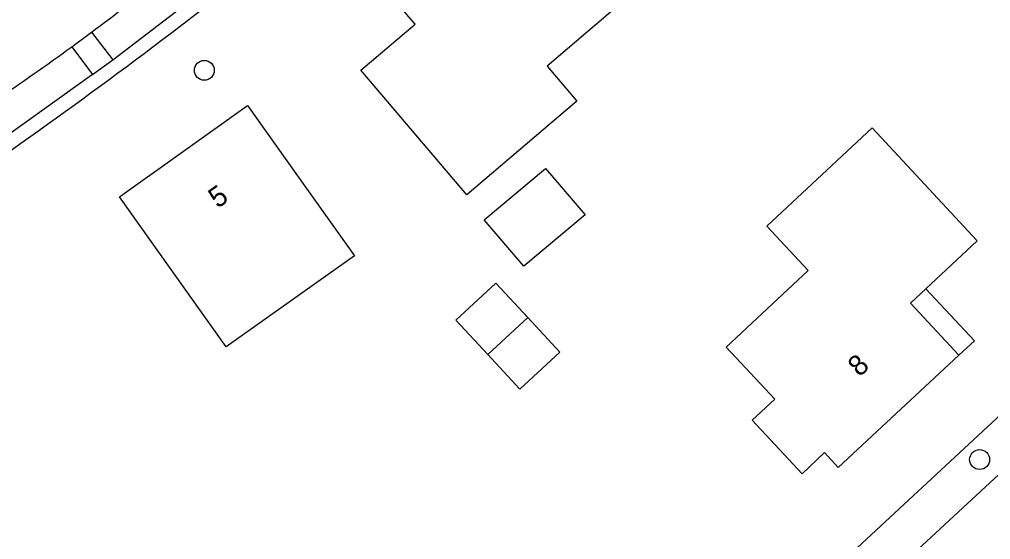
# Model space of a CAD drawing. Extents: x 162675 to 163482, y 379761 to 381227.
# Drawn here: x 163252.7 to 163300.37, y 380905.56 to 380931.1 of the extents above; entities that cross this region are included whole.
import ezdxf

# ---------------------------------------------------------------- set-up
doc = ezdxf.new("R2010")
doc.units = 0
for name, color, linetype in [('IMGEO_Berm_groen', 7, 'Continuous'), ('IMGEO_Boom', 7, 'Continuous'), ('IMGEO_Haag', 7, 'Continuous'), ('IMGEO_Pand', 7, 'Continuous'), ('IMGEO_Pand_nummerreeks', 7, 'Continuous'), ('IMGEO_Pand_overbouw', 7, 'Continuous'), ('IMGEO_Parkeervlak_halfverhard', 7, 'Continuous'), ('IMGEO_Rijbaan_lokaal_gesloten', 7, 'Continuous'), ('IMGEO_Voetpad_open', 7, 'Continuous')]:
    doc.layers.add(name, color=color, linetype=linetype)

msp = doc.modelspace()

# ---------------------------------------------------------------- linework, layer by layer
at = {"layer": 'IMGEO_Berm_groen'}
msp.add_lwpolyline([(163278.098, 380890.562), (163302.041, 380912.777)], dxfattribs=at)
at = {"layer": 'IMGEO_Boom'}
for centre in [(163261.779, 380928.597), (163299.834, 380909.487)]:
    msp.add_circle(centre, 0.489, dxfattribs=at)
at = {"layer": 'IMGEO_Haag'}
msp.add_arc((163095.383, 381147.201), 272.283, 301.26259, 308.46483, dxfattribs=at)
at = {"layer": 'IMGEO_Pand'}
for points in [[(163272.637, 380935.682), (163276.199, 380938.643), (163276.806, 380937.922), (163277.935, 380938.883), (163280.268, 380936.141), (163279.118, 380935.162), (163282.041, 380931.727), (163278.606, 380928.803), (163279.89, 380927.294), (163280.071, 380927.082), (163274.67, 380922.486), (163270.866, 380926.955), (163269.468, 380928.597), (163272.133, 380930.865), (163270.614, 380932.649), (163273.28, 380934.918), (163272.637, 380935.682)], [(163257.609, 380922.38), (163263.9, 380926.863), (163266.801, 380922.792), (163269.149, 380919.497), (163262.858, 380915.014), (163260.51, 380918.309), (163257.609, 380922.38)], [(163289.384, 380920.952), (163294.56, 380925.767), (163299.721, 380920.22), (163297.196, 380917.871), (163296.437, 380917.165), (163298.814, 380914.61), (163292.897, 380909.095), (163292.215, 380909.827), (163291.121, 380908.79), (163288.672, 380911.424), (163289.774, 380912.45), (163287.391, 380915.013), (163291.421, 380918.761), (163289.384, 380920.952)], [(163275.515, 380921.262), (163278.531, 380923.775), (163280.472, 380921.501), (163277.455, 380918.988), (163275.515, 380921.262)], [(163275.691, 380914.641), (163274.122, 380916.336), (163276.084, 380918.152), (163277.653, 380916.458)], [(163277.653, 380916.458), (163279.222, 380914.764), (163277.261, 380912.947), (163275.691, 380914.641)], [(163277.653, 380916.458), (163275.691, 380914.641)]]:
    msp.add_lwpolyline(points, dxfattribs=at)
at = {"layer": 'IMGEO_Pand_overbouw'}
msp.add_lwpolyline([(163298.814, 380914.61), (163299.575, 380915.314), (163297.196, 380917.871), (163296.437, 380917.165)], close=True, dxfattribs=at)
at = {"layer": 'IMGEO_Parkeervlak_halfverhard'}
for points in [[(163257.282, 380929.108), (163260.911, 380931.872)], [(163256.292, 380928.387), (163252.192, 380925.45)]]:
    msp.add_lwpolyline(points, dxfattribs=at)
at = {"layer": 'IMGEO_Rijbaan_lokaal_gesloten'}
for points in [[(163255.272, 380929.752), (163256.239, 380930.465)], [(163303.486, 380911.264), (163303.421, 380911.205), (163292.603, 380901.179), (163284.042, 380893.331), (163283.878, 380893.181), (163279.38, 380889.205)]]:
    msp.add_lwpolyline(points, dxfattribs=at)
for centre, radius, start, end in [((163184.857, 381026.102), 119.339, 306.73702, 308.85086), ((163187.054, 381023.259), 115.746, 303.81288, 306.11255)]:
    msp.add_arc(centre, radius, start, end, dxfattribs=at)
at = {"layer": 'IMGEO_Voetpad_open'}
for points in [[(163256.239, 380930.465), (163257.282, 380929.108)], [(163255.272, 380929.752), (163256.292, 380928.387)], [(163256.292, 380928.387), (163257.282, 380929.108)]]:
    msp.add_lwpolyline(points, dxfattribs=at)

# ---------------------------------------------------------------- texts
at = {"layer": 'IMGEO_Pand_nummerreeks'}
for s, rotation, p in [('5', 35.4739, (163262.434, 380921.791)), ('8', 42.9809, (163293.94, 380913.511))]:
    msp.add_text(s, height=1, rotation=rotation, dxfattribs=at).set_placement(p)

doc.saveas('drawing.dxf')
